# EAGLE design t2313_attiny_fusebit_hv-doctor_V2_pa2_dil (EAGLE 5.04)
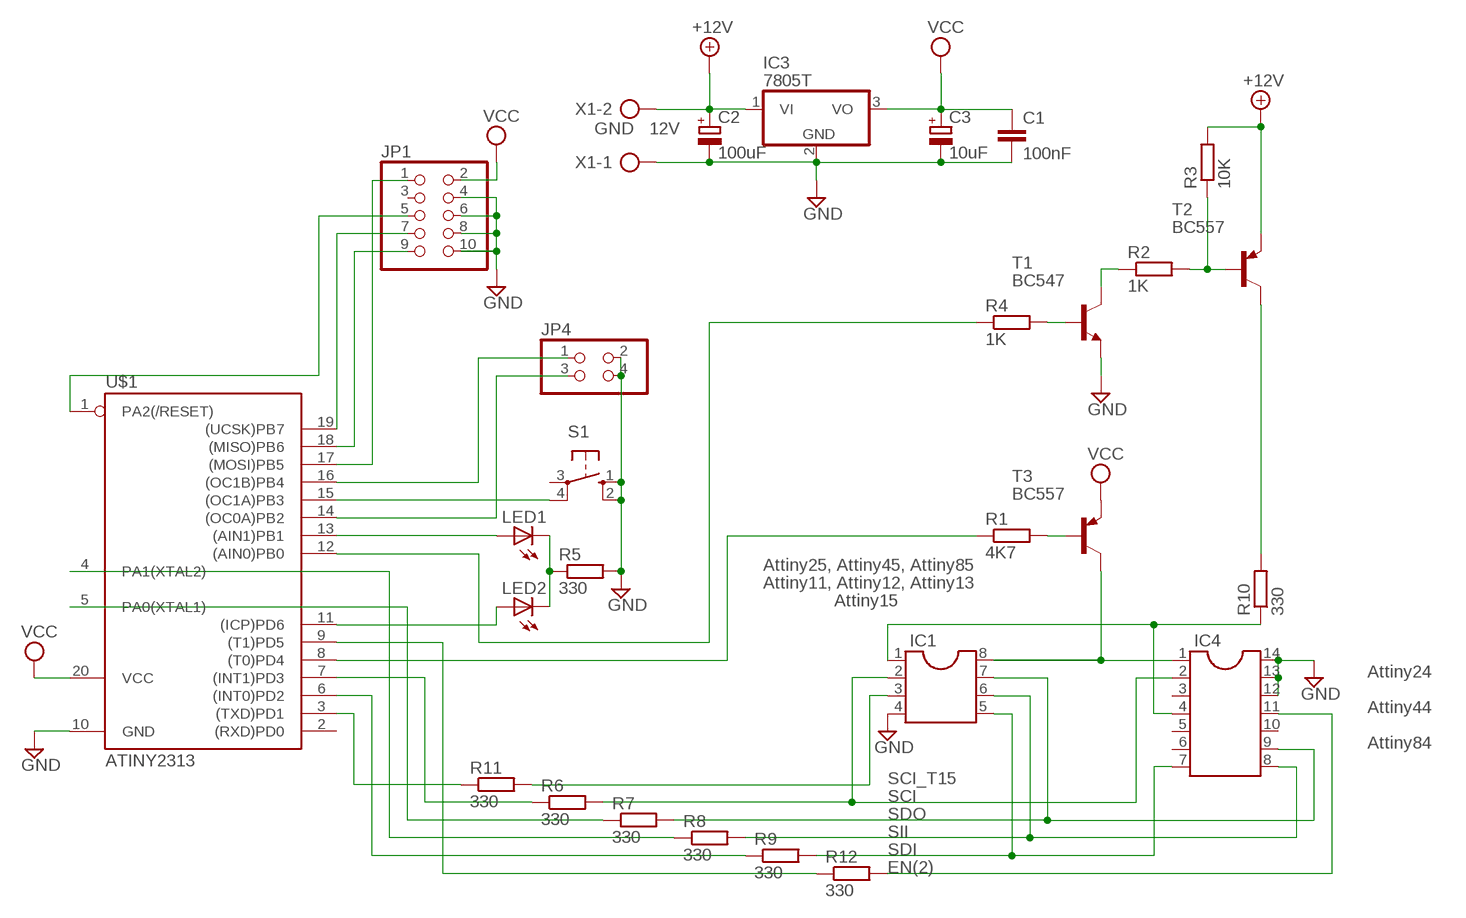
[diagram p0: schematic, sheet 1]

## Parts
C1  100nF  C-EU050-024X044  [C050-024X044]
C2  100uF  CPOL-EUE2.5-6  [E2,5-6]
C3  10uF  CPOL-EUE2.5-6  [E2,5-6]
IC1  DIL8S  [SOCKED-08]
IC3  7805T  [TO220H]
IC4  DIL14S  [SOCKED-14]
JP1  PINHD-2X5  [2X05]
JP4  PINHD-2X2  [2X02]
LED1  LED3MM  [LED3MM]
LED2  LED3MM  [LED3MM]
R1  4K7  R-EU_0207/10  [0207/10]
R2  1K  R-EU_0207/10  [0207/10]
R3  10K  R-EU_0207/10  [0207/10]
R4  1K  R-EU_0207/10  [0207/10]
R5  330  R-EU_0207/10  [0207/10]
R6  330  R-EU_0207/10  [0207/10]
R7  330  R-EU_0207/10  [0207/10]
R8  330  R-EU_0207/10  [0207/10]
R9  330  R-EU_0207/10  [0207/10]
R10  330  R-EU_0207/10  [0207/10]
R11  330  R-EU_0207/10  [0207/10]
R12  330  R-EU_0207/10  [0207/10]
S1  10-XX  [B3F-10XX]
T1  BC547  BC547A-NPN-TO92-EBC  [TO92-EBC]
T2  BC557  BC557A-PNP-TO92-EBC  [TO92-EBC]
T3  BC557  BC557A-PNP-TO92-EBC  [TO92-EBC]
U$1  ATINY2313  TINY2313-*P*  [DIL20]
X1  GND 12V  AK500/2  [AK500/2]

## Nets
+12V: C2.+ IC3.1(VI) R3.2 T2.E X1.2
GND: C1.2 C2.- C3.- IC1.4 IC3.2(GND) IC4.12 IC4.13 IC4.14 JP1.4 JP1.6 JP1.8 JP1.10 JP4.2 JP4.4 R5.2 S1.1(S) S1.2(S1) T1.E U$1.10(GND) X1.1
N$1: R4.1 U$1.12((AIN0)PB0)
N$2: R1.1 U$1.8((T0)PD4)
N$3: R7.1 U$1.5(PA0(XTAL1))
N$4: R8.1 U$1.4(PA1(XTAL2))
N$5: LED1.K(C) LED2.K(C) R5.1
N$6: R1.2 T3.B
N$7: IC1.1 IC4.4 R10.1
N$8: R2.2 R3.1 T2.B
N$9: R2.1 T1.C
N$10: R4.2 T1.B
N$11: LED1.A U$1.13((AIN1)PB1)
N$12: JP1.5 U$1.1(PA2(/RESET))
N$13: JP1.7 U$1.19((UCSK)PB7)
N$14: JP1.9 U$1.18((MISO)PB6)
N$15: JP1.1 U$1.17((MOSI)PB5)
N$16: IC4.11 R12.2
N$18: JP4.1 U$1.16((OC1B)PB4)
N$19: R6.1 U$1.7((INT1)PD3)
N$20: LED2.A U$1.11((ICP)PD6)
N$21: R12.1 U$1.9((T1)PD5)
N$22: R9.1 U$1.6((INT0)PD2)
N$23: JP4.3 U$1.14((OC0A)PB2)
N$24: S1.4(P1) U$1.15((OC1A)PB3)
N$25: R10.2 T2.C
N$26: IC1.3 R11.2
N$27: R11.1 U$1.3((TXD)PD1)
N$29: IC1.8 IC4.1 T3.C
SCI: IC1.2 IC4.2 R6.2
SDI: IC1.5 IC4.7 R9.2
SDO: IC1.7 IC4.9 R7.2
SII: IC1.6 IC4.8 R8.2
VCC: C1.1 C3.+ IC3.3(VO) JP1.2 T3.E U$1.20(VCC)
Unconnected: IC4.3 IC4.5 IC4.6 IC4.10 JP1.3 S1.3(P) U$1.2((RXD)PD0)

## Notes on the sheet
- Attiny25, Attiny45, Attiny85
- Attiny11, Attiny12, Attiny13
- Attiny15
- Attiny24
- Attiny44
- Attiny84
- SCI_T15
- SCI
- SDO
- SII
- SDI
- EN(2)

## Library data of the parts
C1 = rcl:C-EU: CAPACITOR, European symbol
C2 C3 = rcl:CPOL-EU: POLARIZED CAPACITOR, European symbol
IC1 = ic-package:DIL8: Dual In Line
IC3 = linear:78*: Positive VOLTAGE REGULATOR Source: http://cache.national.com/ds/LM/LM78L05.pdf http://www.fairchildsemi.com/ds/LM/LM7805.pdf
IC4 = ic-package:DIL14: Dual In Line
JP1 = pinhead:PINHD-2X5: PIN HEADER
JP4 = pinhead:PINHD-2X2: PIN HEADER
LED1 LED2 = led:LED: LED
R1-R12 = rcl:R-EU_: RESISTOR, European symbol
S1 = switch-omron:10-XX: OMRON SWITCH
T1 = transistor:*-NPN-: NPN Transistror
T2 T3 = transistor:*-PNP-: PNP Transistror
U$1 = avr-6:TINY2313*: Atmel Tiny2313 2K Flash, 128 bytes EEPROM, 128 bytes RAM
X1 = con-ptr500:AK500/2: CONNECTOR

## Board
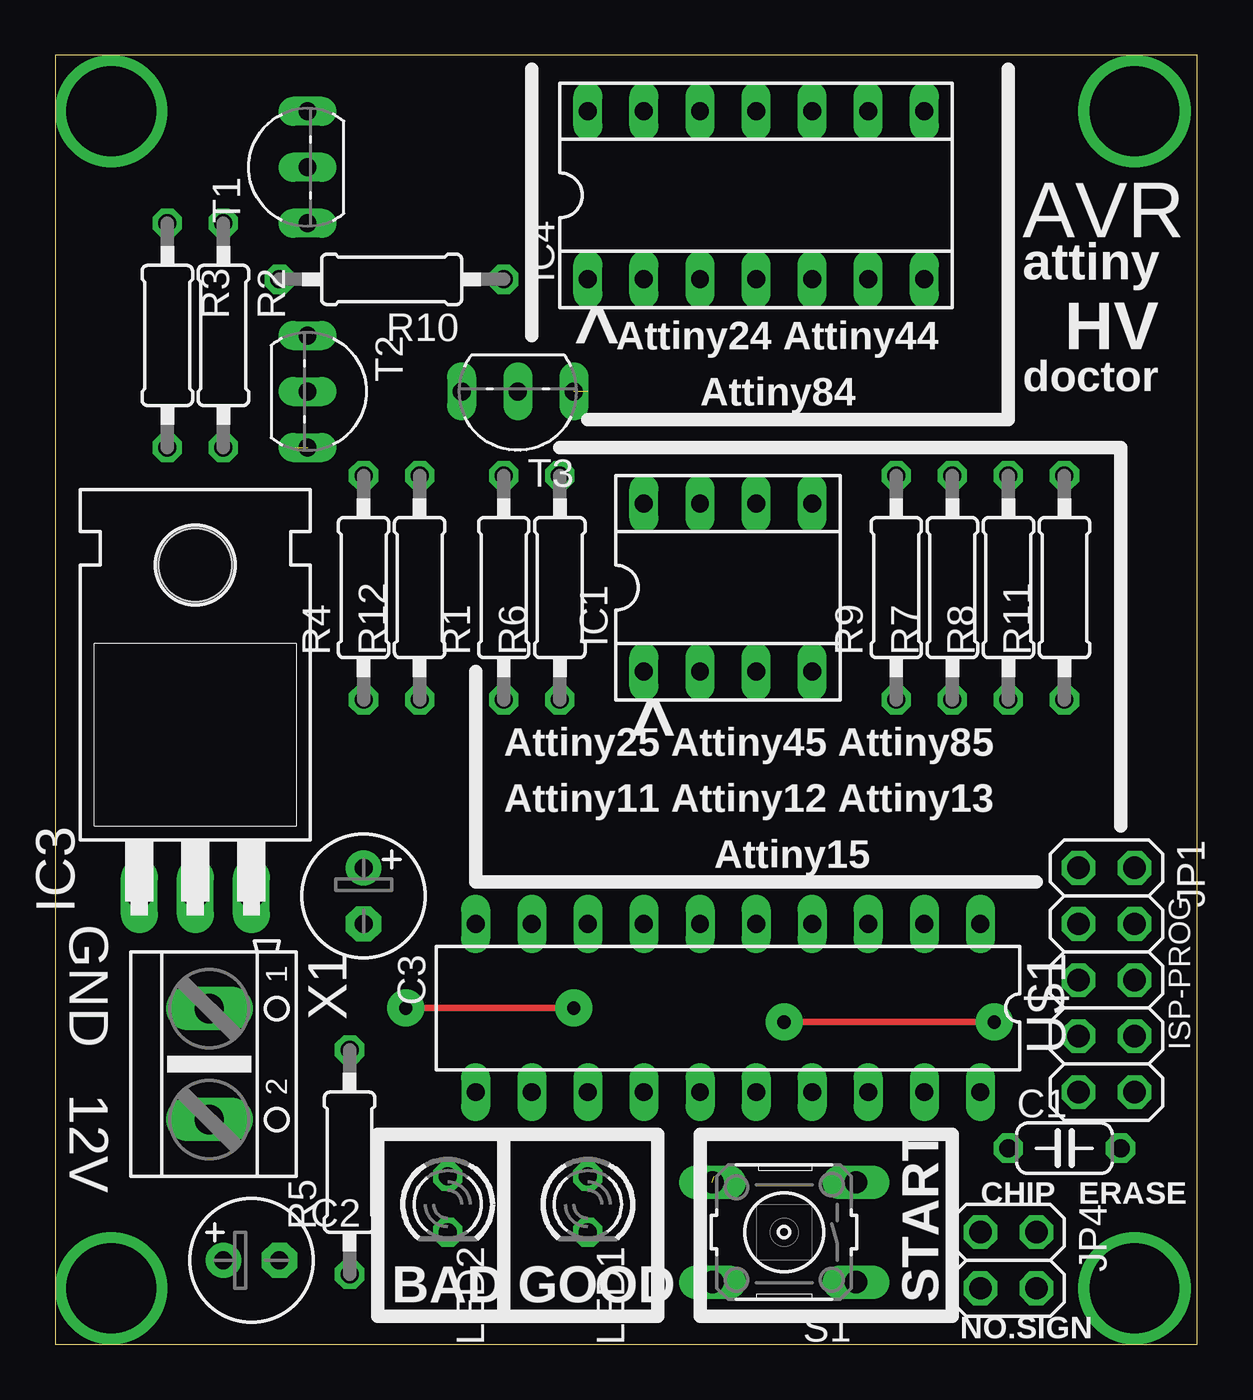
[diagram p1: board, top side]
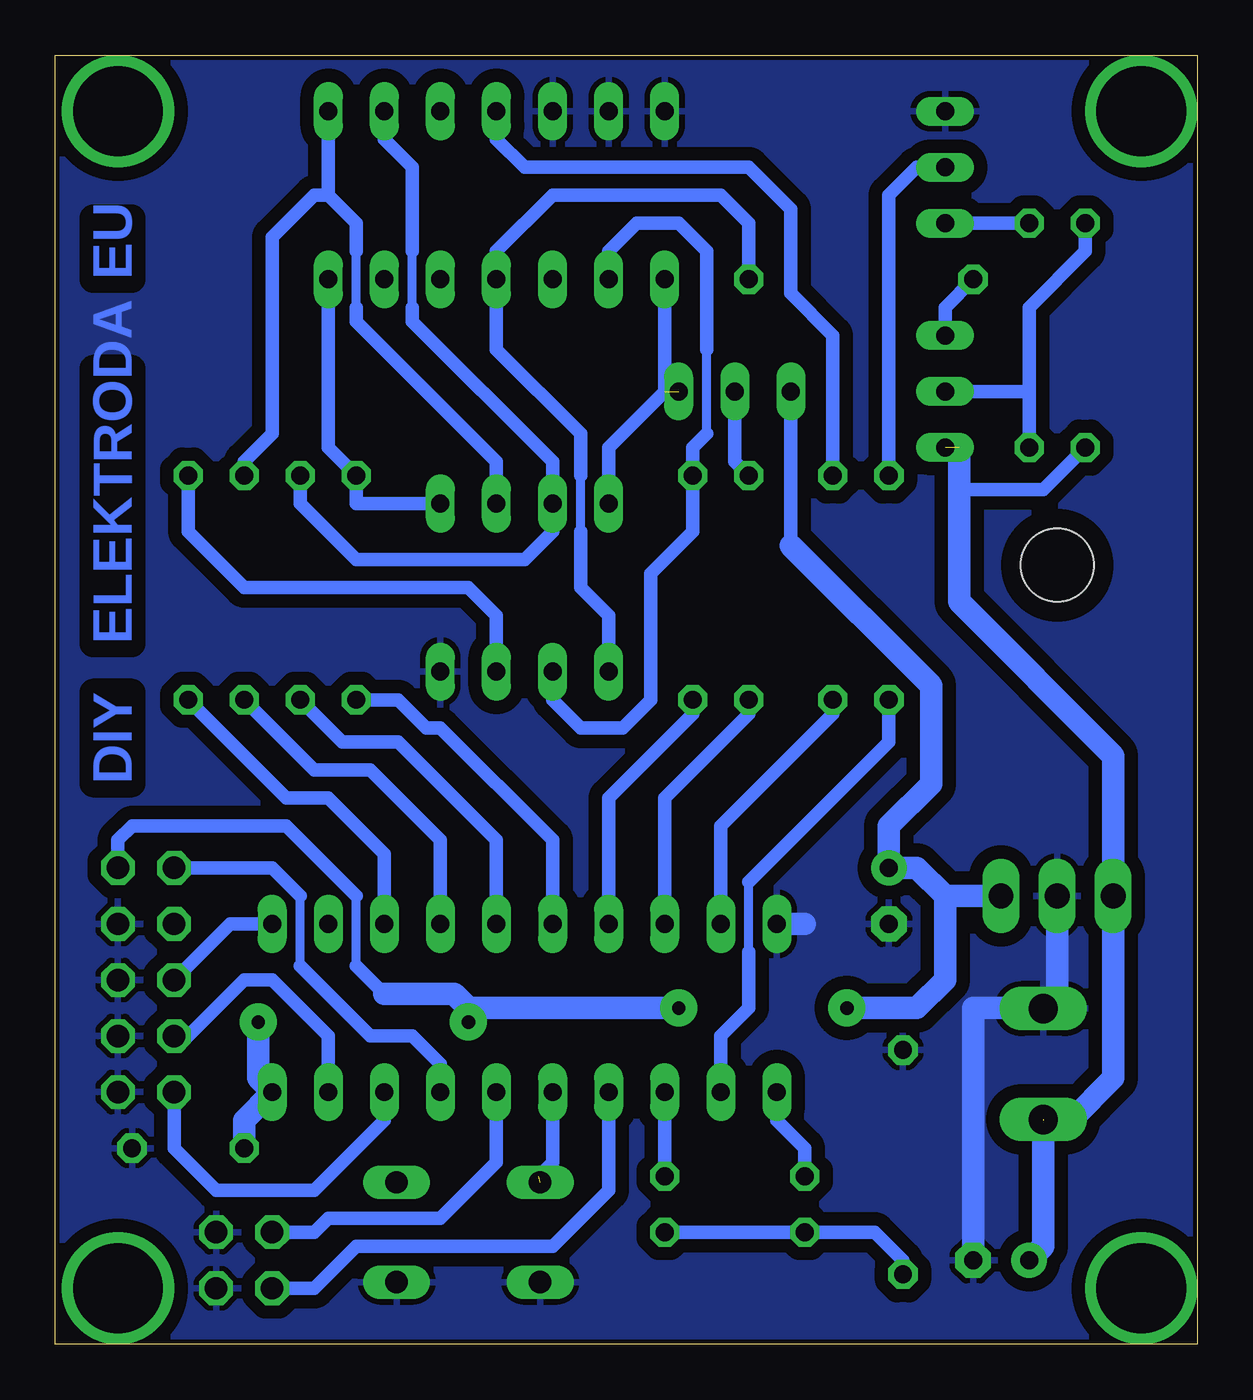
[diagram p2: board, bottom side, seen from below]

Size 51.74 x 58.41 mm. Coordinates in mm from the lower left corner, seen from the top.
Outline: 0,0 51.74,0 51.74,58.41 0,58.41 0,0
Copper layers (1*16): Top 0.035mm / dielectric 1.5mm / Bottom 0.035mm
Design rules "default *": minimum track width 10mil, minimum drill 24mil, track to track 24mil, track to pad 24mil, pad to pad 24mil, via to via 24mil, smd to smd 24mil, copper to edge 8mil, drill to drill 8mil, minimum pad ring 10mil, minimum via ring 8mil, stop-mask expansion 4mil, vias tented up to drill 0mil, thermal gap 10mil

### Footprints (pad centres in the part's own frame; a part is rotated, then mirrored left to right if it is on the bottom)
C050-024X044 = drill 0.813 octagon: 1 -2.54,0; 2 2.54,0
E2,5-6 = drill 0.813 pad 1.6 round: + -1.27,0 | drill 0.813 pad 1.6 octagon: - 1.27,0
SOCKED-08 = drill 0.813 long: 1 -3.81,-3.81; 2 -1.27,-3.81; 3 1.27,-3.81; 4 3.81,-3.81; 5 3.81,3.81; 6 1.27,3.81; 7 -1.27,3.81; 8 -3.81,3.81
TO220H = drill 1.118 long: 1 -2.54,-10.16; 2 0,-10.16; 3 2.54,-10.16 | hole 3.302: 0,4.826
SOCKED-14 = drill 0.813 long: 1 -7.62,-3.81; 2 -5.08,-3.81; 3 -2.54,-3.81; 4 0,-3.81; 5 2.54,-3.81; 6 5.08,-3.81; 7 7.62,-3.81; 8 7.62,3.81; 9 5.08,3.81; 10 2.54,3.81; 11 0,3.81; 12 -2.54,3.81; 13 -5.08,3.81; 14 -7.62,3.81
2X05 = drill 1.016 octagon: 1 -5.08,-1.27; 2 -5.08,1.27; 3 -2.54,-1.27; 4 -2.54,1.27; 5 0,-1.27; 6 0,1.27; 7 2.54,-1.27; 8 2.54,1.27; 9 5.08,-1.27; 10 5.08,1.27
2X02 = drill 1.016 octagon: 1 -1.27,-1.27; 2 -1.27,1.27; 3 1.27,-1.27; 4 1.27,1.27
LED3MM = drill 0.813 octagon: A -1.27,0; K 1.27,0
0207/10 = drill 0.813 octagon: 1 -5.08,0; 2 5.08,0
B3F-10XX = drill 1.016 long: 1 -3.251,2.261; 2 3.251,2.261; 3 -3.251,-2.261; 4 3.251,-2.261
TO92-EBC = drill 0.813 long: B 0,-1.27; C -2.54,-1.27; E 2.54,-1.27
DIL20 = drill 0.813 long: 1 -11.43,-3.81; 2 -8.89,-3.81; 3 -6.35,-3.81; 4 -3.81,-3.81; 5 -1.27,-3.81; 6 1.27,-3.81; 7 3.81,-3.81; 8 6.35,-3.81; 9 8.89,-3.81; 10 11.43,-3.81; 11 11.43,3.81; 12 8.89,3.81; 13 6.35,3.81; 14 3.81,3.81; 15 1.27,3.81; 16 -1.27,3.81; 17 -3.81,3.81; 18 -6.35,3.81; 19 -8.89,3.81; 20 -11.43,3.81
AK500/2 = drill 1.321 long: 1 -2.515,0; 2 2.515,0

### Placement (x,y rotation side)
C1  45.72,8.89 0 top
C2  8.89,3.81 0 top
C3  13.97,20.32 270 top
IC1  30.48,34.29 0 top
IC3  6.35,30.48 0 top
IC4  31.75,52.07 0 top
JP1  47.62,16.51 270 top
JP4  43.18,3.81 270 top
LED1  24.13,6.35 270 top
LED2  17.78,6.35 270 top
R1  20.32,34.29 90 top
R2  7.62,45.72 270 top
R3  5.08,45.72 270 top
R4  13.97,34.29 90 top
R5  13.34,8.26 90 top
R6  22.86,34.29 90 top
R7  40.64,34.29 90 top
R8  43.18,34.29 90 top
R9  38.1,34.29 90 top
R10  15.24,48.26 180 top
R11  45.72,34.29 90 top
R12  16.51,34.29 90 top
S1  33.02,5.08 180 top
T1  10.16,53.34 90 top
T2  12.7,43.18 270 top
T3  20.95,41.91 180 top
U$1  30.48,15.24 180 top
X1  6.99,12.7 270 top

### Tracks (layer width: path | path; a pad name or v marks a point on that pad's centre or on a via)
+12V  (2 unrouted)
  Bottom 0.61: IC3.1 3.81,19.68 | 10.79,38.73 6.99,38.73 R3.2
  Bottom 1.016: C2.+ 6.99,4.45 6.99,10.16 5.71,10.16 3.81,12.06 IC3.1 3.81,26.67 10.79,33.66 10.79,38.73 10.79,40.64
GND
  Bottom 0.61: IC3.2 6.35,21.59
  Bottom 1.016: IC3.2 6.35,15.24 10.16,15.24 C2.- | U$1.10 17.78,19.05
  pour Bottom: 0,58.42 52.07,58.42 52.07,0 0,0
N$1
  Bottom 0.406: 20.32,17.78 20.32,20.95
  Bottom 0.61: 20.32,17.78 20.32,15.24 21.59,13.97 U$1.12 | R4.1 13.97,27.3 20.32,20.95
N$2
  Bottom 0.61: R1.1 20.32,28.57 24.13,24.77 U$1.8
N$3
  Bottom 0.61: R7.1 38.73,27.3 36.2,27.3 31.75,22.86 U$1.5
N$4
  Bottom 0.61: R8.1 40.01,26.04 37.47,26.04 34.29,22.86 U$1.4
N$5
  Bottom 0.61: R5.1 13.34,3.81 14.61,5.08 LED2.K LED1.K
N$6
  Bottom 0.61: R1.2 20.95,40.01 T3.B
N$7
  Bottom 0.406: 27.94,36.83 27.94,39.37
  Bottom 0.61: IC1.1 26.67,33.02 27.94,34.29 27.94,36.83 | 27.94,39.37 27.94,41.27 31.75,45.09 IC4.4 31.75,49.53 29.21,52.07 21.59,52.07 20.32,50.8 R10.1
N$8
  Bottom 0.61: R3.1 5.08,49.53 7.62,46.99 7.62,43.18 | R2.2 7.62,43.18 | 7.62,43.18 T2.B
N$9
  Bottom 0.61: R2.1 T1.C
N$10
  Bottom 0.61: R4.2 13.97,52.07 12.7,53.34 T1.B
N$11
  Bottom 0.61: LED1.A 24.13,10.16 U$1.13
N$12
  Bottom 0.61: U$1.1 43.81,19.05 JP1.5
N$13
  Bottom 0.61: U$1.19 39.37,13.97 41.91,16.51 43.18,16.51 45.72,13.97 JP1.7
N$14
  Bottom 0.61: U$1.18 36.83,10.16 40.01,6.99 44.45,6.99 46.35,8.89 JP1.9
N$15
  Bottom 0.406: 40.64,17.14 40.64,20.32
  Bottom 0.61: U$1.17 34.29,12.7 35.56,13.97 37.47,13.97 40.64,17.14 | 40.64,20.32 41.91,21.59 JP1.1
N$16
  Bottom 0.61: IC4.11 31.75,54.61 30.48,53.34 20.32,53.34 18.41,51.44 18.41,47.62 16.51,45.72 R12.2
N$17  (via drill 4.06 pad 5.08)
  other vias: 2.54,55.88
N$18
  Bottom 0.61: U$1.16 31.75,8.26 34.29,5.71 39.37,5.71 40.01,5.08 JP4.1
N$19
  Bottom 0.61: R6.1 22.86,28.57 26.67,24.77 U$1.7
N$20
  Bottom 0.61: LED2.A 17.78,8.89 19.05,10.16 U$1.11
N$21
  Bottom 0.61: R12.1 16.51,28.57 21.59,23.5 U$1.9
N$22
  Bottom 0.61: R9.1 36.2,29.21 34.92,27.94 34.29,27.94 29.21,22.86 U$1.6
N$23
  Bottom 0.61: U$1.14 26.67,6.99 29.21,4.45 38.1,4.45 40.01,2.54 JP4.3
N$24  (1 unrouted)
  Bottom 0.61: 29.84,7.62 29.21,8.26 U$1.15
N$25
  Bottom 0.61: R10.2 11.43,46.99 T2.C
N$26
  Bottom 0.61: IC1.3 31.75,33.02 33.02,34.29 43.18,34.29 45.72,36.83 R11.2
N$27
  Bottom 0.61: R11.1 41.27,24.77 39.37,24.77 36.83,22.23 U$1.3
N$28  (via drill 4.06 pad 5.08)
  other vias: 2.54,2.54
N$29  (1 unrouted)
  Bottom 0.61: IC4.1 24.13,43.18 26.67,40.64 IC1.8
N$32  (via drill 4.06 pad 5.08)
  other vias: 48.9,2.54
N$33  (via drill 4.06 pad 5.08)
  other vias: 48.9,55.88
SCI
  Bottom 0.406: 22.23,41.27 22.23,45.09
  Bottom 0.61: IC4.2 26.67,49.53 25.4,50.8 23.5,50.8 22.23,49.53 22.23,45.09 | 22.23,41.27 22.86,40.64 R6.2 22.86,36.83 24.77,34.92 24.77,29.21 26.04,27.94 27.94,27.94 29.21,29.21 IC1.2
SDI
  Bottom 0.61: IC4.7 39.37,40.64 R9.2 38.1,38.1 IC1.5
SDO
  Bottom 0.406: 35.56,46.99 35.56,49.53
  Bottom 0.61: IC4.9 36.83,54.61 35.56,53.34 35.56,49.53 | 35.56,46.99 35.56,46.35 29.21,40.01 IC1.7 29.21,36.83 30.48,35.56 38.1,35.56 40.64,38.1 R7.2
SII
  Bottom 0.406: 38.1,46.99 38.1,49.53
  Bottom 0.61: 39.37,52.07 IC4.8 | 39.37,52.07 38.1,50.8 38.1,49.53 | 38.1,46.99 38.1,46.35 31.75,40.01 IC1.6 | 39.37,52.07 40.01,52.07 41.91,50.16 41.91,41.27 43.18,40.01 R8.2
VCC  (via drill 0.6 pad 1.68)
  Top 0.305: v33.02,14.61 v42.55,14.61 | v15.88,15.24 v23.5,15.24
  Bottom 0.406: 38.1,17.14 38.1,20.32
  Bottom 0.61: 36.83,15.88 38.1,17.14 | 38.1,20.32 41.27,23.5 48.26,23.5 48.9,22.86 JP1.2 | 18.41,36.2 T3.E
  Bottom 1.016: 18.41,36.2 12.06,29.84 12.06,25.4 13.97,23.5 C3.+ 12.7,21.59 11.43,20.32 | 33.02,15.24 33.66,15.88 36.83,15.88 | v23.5,15.24 33.02,15.24 | 11.43,20.32 IC3.3 | 33.02,15.24 v33.02,14.61 | v42.55,14.61 42.55,12.06 U$1.20 43.18,10.16 C1.1 | 11.43,20.32 11.43,16.51 12.7,15.24 v15.88,15.24

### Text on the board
Bottom: EU | ELEKTRODA | DIY
tPlace: AVR | attiny | Attiny24 Attiny44 | HV | ^ | Attiny84 | doctor | Attiny25 Attiny45 Attiny85 | ^ | Attiny11 Attiny12 Attiny13 | Attiny15 | ISP-PROG | CHIP | ERASE | BAD | GOOD | START | NO.SIGN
